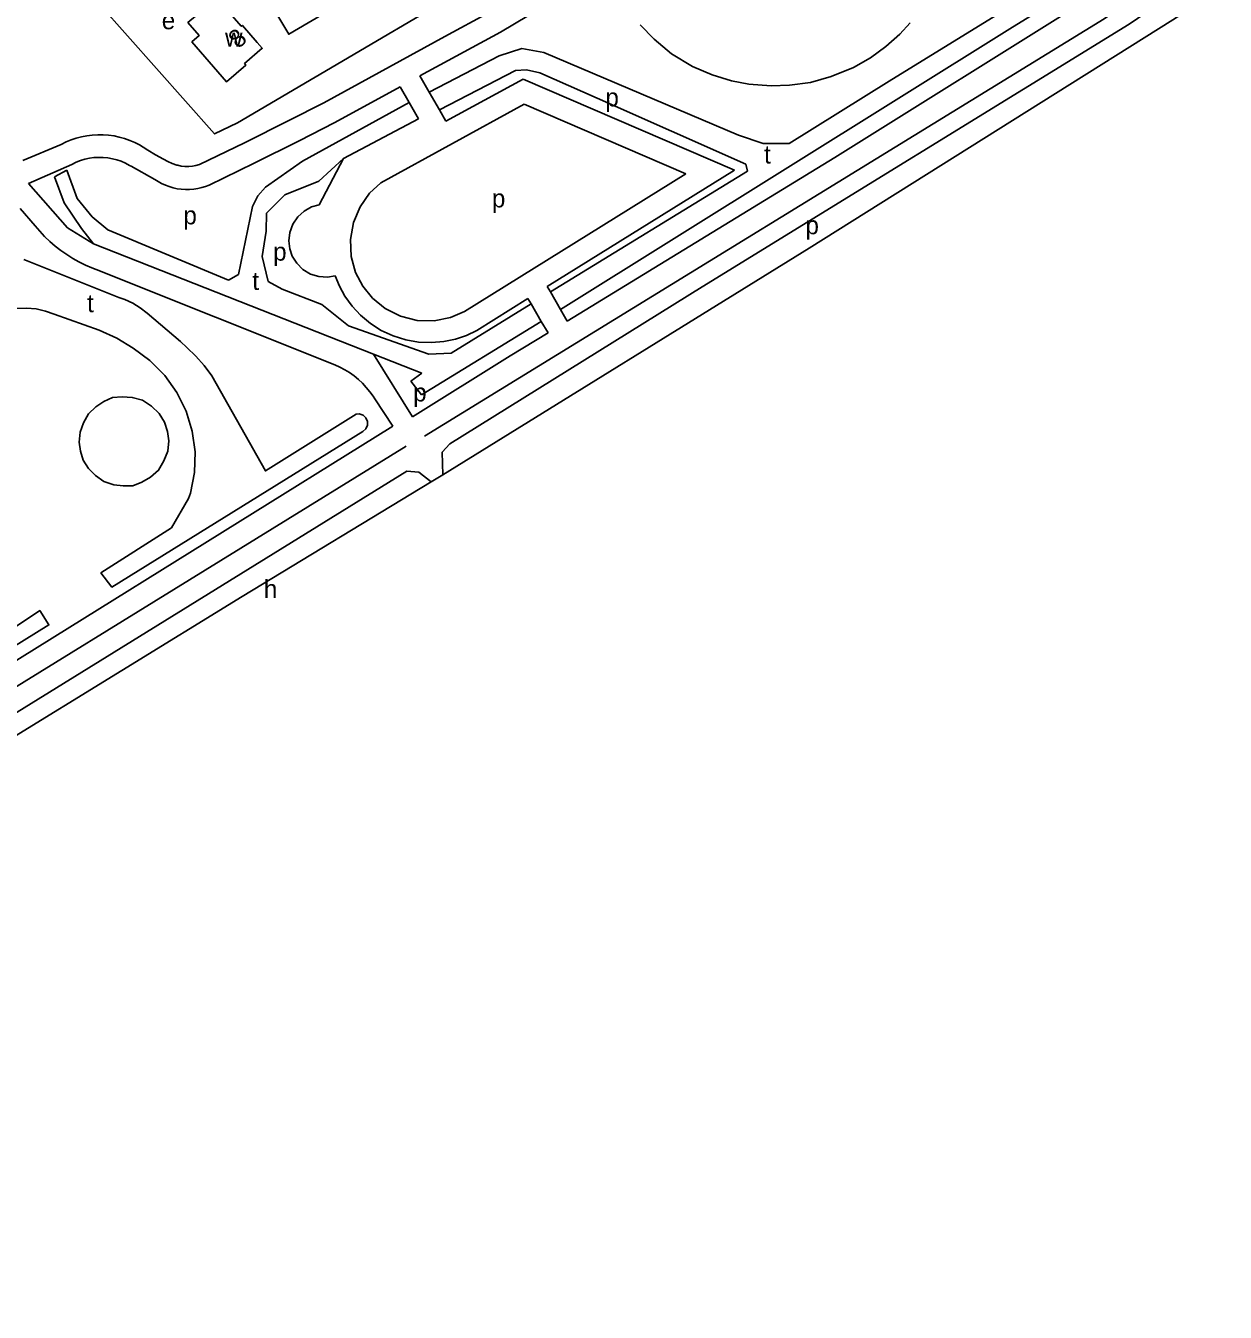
# Model space of a CAD drawing. Extents: x 158848 to 160613, y 385889 to 387762.
# Drawn here: x 160246.8 to 160511.5, y 386125.6 to 386409.7 of the extents above; entities that cross this region are included whole.
import ezdxf

# ---------------------------------------------------------------- set-up
doc = ezdxf.new("R2010")
doc.units = 0
for name, color, linetype in [('BLT_Basislijn', 7, 'Continuous'), ('BLT_Bebouwing', 7, 'Continuous'), ('BLT_Centroide', 7, 'Continuous'), ('BLT_Huisnummer', 7, 'Continuous')]:
    doc.layers.add(name, color=color, linetype=linetype)

msp = doc.modelspace()

# ---------------------------------------------------------------- linework, layer by layer
at = {"layer": 'BLT_Basislijn'}
for p, q in [((160501.39, 386436.96), (160437.36, 386397.4)), ((160464.55, 386409.35), (160503.8, 386433.49)), ((160364.79, 386347), (160464.55, 386409.35)), ((160312.59, 386392.63), (160339.26, 386407.27)), ((160356.27, 386404.65), (160351.29, 386402.99)), ((160361.1, 386403.74), (160356.27, 386404.65)), ((160404.14, 386385.47), (160361.1, 386403.74)), ((160351.29, 386402.99), (160335.84, 386394.97)), ((160333.76, 386398.6), (160335.84, 386394.97)), ((160338.07, 386391.09), (160354.91, 386399.78)), ((160356.56, 386397.87), (160339.52, 386388.55)), ((160354.91, 386399.78), (160357.33, 386399.91)), ((160356.56, 386397.87), (160403.2, 386377.78)), ((160357.33, 386399.91), (160360.27, 386399.27)), ((160360.27, 386399.27), (160372.9, 386393.65)), ((160437.36, 386397.4), (160415.31, 386383.66)), ((160314.99, 386388.25), (160329.4, 386396.15)), ((160329.4, 386396.15), (160331.38, 386392.7)), ((160338.07, 386391.09), (160335.84, 386394.97)), ((160331.38, 386392.7), (160307.84, 386379.73)), ((160356.82, 386392.32), (160325.16, 386374.98)), ((160333.47, 386389.06), (160331.38, 386392.7)), ((160356.82, 386392.32), (160392.45, 386376.97)), ((160372.9, 386393.65), (160405.71, 386379.1)), ((160316.93, 386380.32), (160333.47, 386389.06)), ((160338.07, 386391.09), (160339.52, 386388.55)), ((160254.62, 386383.45), (160246.15, 386379.88)), ((160409.58, 386383.66), (160404.14, 386385.47)), ((160415.31, 386383.66), (160409.58, 386383.66)), ((160256.98, 386379.04), (160247.4, 386374.78)), ((160255.87, 386377.78), (160253.13, 386376.31)), ((160258.11, 386371.53), (160255.87, 386377.78)), ((160270.02, 386378.62), (160275.27, 386375.72)), ((160307.84, 386379.73), (160299.73, 386373.97)), ((160311.46, 386375.34), (160316.93, 386380.32)), ((160316.93, 386380.32), (160311.53, 386370.12)), ((160361.89, 386352.04), (160403.2, 386377.78)), ((160406.09, 386377.57), (160362.59, 386350.86)), ((160405.71, 386379.1), (160406.09, 386377.57)), ((160247.4, 386374.78), (160256.01, 386365.04)), ((160253.13, 386376.31), (160255.28, 386370.55)), ((160303.93, 386372.31), (160311.46, 386375.34)), ((160343.66, 386346.57), (160392.45, 386376.97)), ((160297.97, 386372.11), (160296.8, 386369.77)), ((160299.73, 386373.97), (160297.97, 386372.11)), ((160299.93, 386368.3), (160303.93, 386372.31)), ((160248.84, 386365.46), (160245.54, 386369.26)), ((160255.28, 386370.55), (160259.09, 386364.88)), ((160261.44, 386367.42), (160258.11, 386371.53)), ((160296.8, 386369.77), (160293.77, 386354.72)), ((160264.86, 386364.59), (160261.44, 386367.42)), ((160299.83, 386364.3), (160299.93, 386368.3)), ((160256.01, 386365.04), (160261.72, 386361.48)), ((160259.09, 386364.88), (160261.72, 386361.48)), ((160291.53, 386353.45), (160264.86, 386364.59)), ((160298.95, 386358.73), (160299.83, 386364.3)), ((160261.72, 386361.48), (160323.52, 386337.15)), ((160300.32, 386353.16), (160298.95, 386358.73)), ((160262.29, 386355.82), (160315, 386334.79)), ((160293.77, 386354.72), (160291.53, 386353.45)), ((160303.35, 386351.5), (160300.32, 386353.16)), ((160362.59, 386350.86), (160361.89, 386352.04)), ((160312.14, 386348.08), (160303.35, 386351.5)), ((160346.31, 386342.33), (160357.63, 386349.39)), ((160358.33, 386348.24), (160357.63, 386349.39)), ((160362.59, 386350.86), (160364.79, 386347)), ((160318, 386343.39), (160312.14, 386348.08)), ((160358.33, 386348.24), (160340.67, 386337.33)), ((160358.33, 386348.24), (160360.55, 386344.35)), ((160364.79, 386347), (160366.31, 386344.45)), ((160334.12, 386328.15), (160360.55, 386344.35)), ((160360.55, 386344.35), (160362.1, 386341.88)), ((160335.78, 386337.14), (160318, 386343.39)), ((160323.52, 386337.15), (160332.15, 386323.29)), ((160323.52, 386337.15), (160334.22, 386332.94)), ((160340.67, 386337.33), (160335.78, 386337.14)), ((160334.22, 386332.94), (160331.78, 386331.18)), ((160331.78, 386331.18), (160334.12, 386328.15)), ((160323.8, 386327.27), (160327.81, 386321.26)), ((160338.84, 386310.49), (160336.29, 386308.98))]:
    msp.add_line(p, q, dxfattribs=at)
for points in [[(160234.68, 386446.05), (160243.66, 386436.33), (160288.41, 386385.75), (160293.49, 386388.23), (160363.35, 386429.34), (160366.05, 386430.61), (160366.24, 386431.5), (160361.33, 386438.63)], [(160366.31, 386344.45), (160425.36, 386380.53), (160480.45, 386415), (160500, 386428.76), (160507.31, 386434.02)], [(160334.8, 386319.04), (160484.79, 386411.17), (160500, 386421.75), (160510.25, 386428.93)], [(160379.27, 386430.05), (160373.17, 386426.99), (160349.07, 386412.59), (160339.26, 386407.27)], [(160381.51, 386425.57), (160375.58, 386422.61), (160351.55, 386408.25), (160333.76, 386398.6)], [(160338.84, 386310.49), (160338.69, 386315.49), (160340.41, 386317.33), (160396.05, 386351.99), (160490.36, 386410.03), (160500, 386416.63), (160511.55, 386424.58)], [(160338.84, 386310.49), (160419.7, 386360.52), (160500, 386410.93), (160507.85, 386416.12)], [(160382.4, 386409.86), (160385.48, 386406.65), (160389.35, 386403.47), (160393.95, 386400.67), (160398.3, 386398.84), (160402.59, 386397.52), (160406.36, 386396.76), (160411.3, 386396.35), (160415.38, 386396.52), (160419.98, 386397.14), (160424.57, 386398.46), (160429.52, 386400.46), (160433.25, 386402.54), (160436.6, 386405.06), (160439.71, 386407.82), (160442.03, 386410.28)], [(160285.14, 386378.98), (160295.03, 386383.82), (160304.88, 386388.73), (160312.59, 386392.63)], [(160287.29, 386374.47), (160297.23, 386379.33), (160307.13, 386384.26), (160314.99, 386388.25)], [(160254.62, 386383.45), (160255.69, 386383.98), (160256.8, 386384.44), (160257.94, 386384.82), (160259.1, 386385.13), (160260.28, 386385.36), (160261.47, 386385.51), (160262.67, 386385.58), (160263.87, 386385.57), (160265.07, 386385.48), (160266.26, 386385.31), (160267.43, 386385.07), (160268.59, 386384.74), (160269.72, 386384.34), (160270.82, 386383.86), (160271.89, 386383.32), (160272.66, 386382.86)], [(160256.98, 386379.04), (160257.9, 386379.49), (160258.85, 386379.86), (160259.82, 386380.16), (160260.82, 386380.38), (160261.83, 386380.52), (160262.85, 386380.58), (160263.87, 386380.57), (160264.89, 386380.47), (160265.89, 386380.29), (160266.88, 386380.04), (160267.85, 386379.71), (160268.78, 386379.3), (160269.68, 386378.82), (160270.02, 386378.62)], [(160277.19, 386380.16), (160275.43, 386381.13), (160273.7, 386382.18), (160272.66, 386382.86)], [(160280.12, 386378.9), (160279.1, 386379.25), (160278.12, 386379.67), (160277.19, 386380.16)], [(160285.14, 386378.98), (160284.35, 386378.76), (160283.55, 386378.62), (160282.74, 386378.56), (160281.92, 386378.57), (160281.11, 386378.67), (160280.32, 386378.84), (160280.12, 386378.9)], [(160275.27, 386375.72), (160276, 386375.25), (160276.77, 386374.82), (160277.59, 386374.45), (160278.43, 386374.13), (160279.31, 386373.87), (160280.21, 386373.67), (160281.12, 386373.54), (160282.04, 386373.48), (160282.95, 386373.49), (160283.86, 386373.56), (160284.76, 386373.7), (160285.63, 386373.9), (160286.48, 386374.16), (160287.29, 386374.47)], [(160325.16, 386374.98), (160322.65, 386372.65), (160320.56, 386369.69), (160319.1, 386366.21), (160318.45, 386362.46), (160318.64, 386358.7), (160319.6, 386355.2), (160321.17, 386352.15), (160323.32, 386349.49), (160326.13, 386347.19), (160329.49, 386345.5), (160333.19, 386344.58), (160336.96, 386344.5), (160340.52, 386345.22), (160343.66, 386346.57)], [(160311.53, 386370.12), (160309.87, 386369.64), (160308.25, 386368.74), (160306.82, 386367.44), (160305.73, 386365.81), (160305.07, 386363.99), (160304.87, 386362.14), (160305.06, 386360.42), (160305.62, 386358.78), (160306.6, 386357.21), (160307.97, 386355.84), (160309.65, 386354.83), (160311.5, 386354.26), (160313.35, 386354.15), (160315.06, 386354.43)], [(160248.84, 386365.46), (160249.86, 386364.26), (160250.95, 386363.11), (160252.08, 386362.02), (160253.28, 386360.99), (160254.52, 386360.02), (160255.81, 386359.11), (160257.15, 386358.27), (160258.52, 386357.5), (160259.94, 386356.8), (160261.39, 386356.17), (160262.29, 386355.82)], [(160244.79, 386347.19), (160246.93, 386347.31), (160249.06, 386347.14), (160251.15, 386346.65), (160253.05, 386345.93), (160263, 386342.43), (160266.87, 386340.68), (160270.52, 386338.49), (160274.2, 386335.7), (160277.46, 386332.44), (160280.15, 386328.69), (160282.22, 386324.57), (160283.54, 386320.15), (160284.19, 386315.58), (160284.02, 386310.97), (160283.15, 386306.43), (160282.69, 386305.3), (160278.95, 386298.79), (160263.36, 386288.83), (160265.79, 386285.69), (160321.19, 386320.08), (160321.84, 386320.65), (160322.2, 386321.43), (160322.21, 386322.29), (160321.85, 386323.08), (160321.22, 386323.67), (160320.4, 386323.93), (160319.73, 386323.9), (160299.67, 386311.36), (160287.83, 386332.35), (160286.18, 386334.6), (160284.35, 386336.69), (160282.35, 386338.63), (160280.94, 386339.9), (160273.58, 386346.16), (160272.05, 386347.35), (160270.41, 386348.38), (160268.65, 386349.2), (160267.31, 386349.66), (160246.39, 386358.05)], [(160315.06, 386354.43), (160316, 386352.16), (160317.24, 386349.92), (160318.8, 386347.76), (160320.67, 386345.74), (160322.84, 386343.92), (160325.26, 386342.38), (160327.89, 386341.16), (160330.65, 386340.29), (160333.49, 386339.8), (160336.31, 386339.68), (160339.05, 386339.91), (160341.66, 386340.46), (160344.09, 386341.28), (160346.31, 386342.33)], [(160332.15, 386323.29), (160353.7, 386336.75), (160362.1, 386341.88)], [(160315, 386334.79), (160316.12, 386334.28), (160317.2, 386333.7), (160318.25, 386333.05), (160319.24, 386332.33), (160320.2, 386331.54), (160321.09, 386330.7), (160321.93, 386329.8), (160322.71, 386328.85), (160323.43, 386327.85), (160323.8, 386327.27)], [(160270.38, 386308.09), (160268.3, 386308.03), (160266.19, 386308.3), (160264.04, 386308.99), (160262.21, 386310.32), (160260.63, 386311.88), (160259.48, 386313.74), (160258.87, 386315.69), (160258.57, 386317.71), (160258.8, 386319.88), (160259.54, 386321.97), (160260.61, 386323.97), (160262.24, 386325.52), (160264.02, 386326.69), (160265.92, 386327.54)], [(160265.92, 386327.54), (160268.08, 386327.73), (160270.29, 386327.57), (160272.56, 386326.95), (160274.52, 386325.62), (160276.21, 386324.03), (160277.44, 386322.11), (160278.08, 386320.09), (160278.38, 386317.99), (160278.12, 386315.73), (160277.29, 386313.57), (160276.1, 386311.51), (160274.32, 386309.97), (160272.41, 386308.86), (160270.38, 386308.09)], [(160327.81, 386321.26), (160139.73, 386204.18), (160136.89, 386202.28)], [(160330.77, 386316.8), (160190.68, 386230.45), (160139.18, 386198.54)], [(160336.29, 386308.98), (160333.57, 386311.08), (160330.93, 386311.27), (160200.07, 386230.42), (160097.58, 386166.67), (160060.99, 386143.91), (160053.68, 386139.74), (160037.68, 386133.3), (160036.34, 386132.46), (160037.72, 386129.81), (160040.36, 386125.59)], [(160336.29, 386308.98), (160294.53, 386283.61), (160188.21, 386218.24)], [(160227.23, 386266.13), (160242.66, 386275.91), (160245.17, 386277.36), (160249.85, 386280.52), (160251.9, 386277.37), (160194.65, 386241.84), (160135.16, 386205.07)]]:
    msp.add_lwpolyline(points, dxfattribs=at)
at = {"layer": 'BLT_Bebouwing'}
for points in [[(160314.48, 386420.69), (160311.39, 386418.87), (160309.23, 386422.54), (160303.56, 386419.19), (160303.4, 386419.43), (160298.99, 386416.85), (160301.52, 386412.54), (160301.85, 386411.99), (160302.23, 386412.22), (160304.84, 386407.78), (160314.28, 386413.32), (160314.88, 386412.3), (160318.25, 386414.28)], [(160297.88, 386405.94), (160294.6, 386409.72), (160294.36, 386409.54), (160291.4, 386412.97), (160290.49, 386412.19), (160287.99, 386415.06), (160284.22, 386411.78), (160282.56, 386410.34), (160285.05, 386407.47), (160283.45, 386406.08), (160291.12, 386397.24), (160295.39, 386400.95), (160295.09, 386401.29), (160298.98, 386404.67), (160297.88, 386405.94)]]:
    msp.add_lwpolyline(points, dxfattribs=at)

# ---------------------------------------------------------------- texts
at = {"layer": 'BLT_Centroide'}
for s, p in [('e', (160276.8, 386408.87)), ('w', (160290.77, 386405.05)), ('p', (160374.72, 386391.84)), ('t', (160409.76, 386379.23)), ('p', (160349.67, 386369.54)), ('p', (160281.57, 386365.8)), ('p', (160418.88, 386363.61)), ('p', (160301.38, 386357.78)), ('t', (160296.78, 386351.32)), ('t', (160260.32, 386346.4)), ('p', (160332.29, 386326.69)), ('h', (160299.32, 386283.29))]:
    msp.add_text(s, height=4, dxfattribs=at).set_placement(p)
at = {"layer": 'BLT_Huisnummer'}
msp.add_text('8', height=4, rotation=40.9808, dxfattribs=at).set_placement((160293.67, 386404.42))

doc.saveas('drawing.dxf')
